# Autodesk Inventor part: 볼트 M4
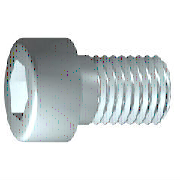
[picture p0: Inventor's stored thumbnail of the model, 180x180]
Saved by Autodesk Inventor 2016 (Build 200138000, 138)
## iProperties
IsCustomPart: 1
Created: 2012-02
Part Number: 볼트 M4
Material: 강철, 연강
Description: 6각머리 태핑 나사
Document SubType Name: Modeling
Standard: KS B 1003
Designer: mduedu
Standards Organization: KS
Language: ko-KR
Size Designation: M 4 x 12
Categories: <MemberInstance><Categories><Category DisplayName="조임쇠" InternalName="e4da775c-781d-43d5-af7c-5136215cf5a6" Mnemonic="FSTN"><Category DisplayName="볼트" InternalN
Density: 1 g/cm^3
Appearance: 강철
Author: mduedu
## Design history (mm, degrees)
sketch "스케치1"
  geometry: L1 (-1, 0)-(12, 0); L2 (12, 0)-(12, 2); L3 (12, 2)-(1.75, 2); L4 (1.75, 2)-(1.32, 2); L5 (1.32, 2)-(0, 2); L6 (0, 2)-(0, 3.5); L7 (0, 3.5)-(-4, 3.5); L8 (-4, 3.5)-(-4, 1.732); L9 (-4, 1.732)-(-2, 1.732); L10 (-2, 1.732)-(-1, 0); L11 (-7.2, 0)-(15.2, 0) reference; L12 (0, -0.7)-(0, 4.2) reference; L13 (1.75, 2)-(0, 2)
  constraints: 22 end point, 6 parallel, 2 collinear, 2 perpendicular, 1 horizontal, 1 point on line
  dimensions: "d1" = 10.25 distance from line of L3.end L2 (= GEL); "d2" = 0.42952 distance of L4.end L3.end (computed from GAL); "d3" = 4 distance between parallel lines of L8 L6 (= KOH); "d4" = 2 distance of L8.end L9.end (= INTI); "d5" = 60 deg angle of L10 L1; "d6" = 4 diameter of L3 L1 (= GD); "d7" = 4 diameter of L5 L1 (= BDM); "d8" = 3.4641 diameter of L9 L1 (= 1.1547 x SW); "d9" = 7 diameter of L7 L1 (= KOD); "d26" = 12 distance between parallel lines of L12 L2 (= NLG)
revolve "본체" sketch "스케치1" stored, may be unused: angle "d10" = 90 deg
sketch "스케치2"
  geometry: L1 (0, -4.9)-(0, 4.9) reference; L2 (-4.9, 0)-(4.9, 0) reference; L3 (1.732, 0)-(0.866, -1.5); L4 (0.866, -1.5)-(-0.866, -1.5); L5 (-0.866, -1.5)-(-1.732, 0); L6 (-1.732, 0)-(-0.866, 1.5); L7 (-0.866, 1.5)-(0.866, 1.5); L8 (0.866, 1.5)-(1.732, 0); 2 further points
  constraints: 12 end point, 1 coincident, 1 horizontal alignment, 1 point on line, 12 other
extrude "슬롯" join sketch "스케치2" stored distance "d11" = 10; taper "d12" = 0 deg
workplane "Work Plane1"
fillet "Fillet2" dims "d30" = 0.1 (= R)
body "Solid1"
fillet "모깎기1" dims "d17" = 0.4 (= RR)
feature "스레드" dims "d13" = 10.25 (= GEL), "d14" = 0
chamfer "모따기1" distance "d15" = 0.42941 (= -0.5 x SPD + 0.5 x GD); stored, may be unused: second distance "d16" = 0.42941 (= GUL), angle "d27" = 45 deg
other parameters: "GD" = 4 (= NND) [user parameter; used in 2 equation terms], "NLG" = 12 [user parameter; used in 1 equation term], "GEL" = 10.25 [user parameter; used in 2 equation terms], "KOD" = 7 [user parameter; used in 1 equation term], "KOH" = 4 [user parameter; used in 1 equation term], "INTI" = 2 [user parameter; used in 1 equation term], "GAL" = 0.42941 (= 0.61345 x PTC) [user parameter; used in 1 equation term], "GUL" = 0.42941 (= 0.61345 x PTC) [user parameter; used in 1 equation term], "BDM" = 4 (= NND) [user parameter; used in 1 equation term], "SW" = 3 [user parameter; used in 2 equation terms], "RR" = 0.4 [user parameter; used in 1 equation term], "SPD" = 3.14117 (= NND - 1.2269 x PTC) [user parameter; used in 1 equation term], "d19" = 0, "d28" = 0, "d29" = 0, "R" = 0.1 [user parameter; used in 1 equation term], "PHH" = 0.2 [user parameter], "GD1" = 3.14117 (= THREADDIA - 1.2269 x PTC) [user parameter], "THREADDIA" = 4 [user parameter; used in 1 equation term], "FAWI" = 45 deg [user parameter], "TPU" = 14.28571 (computed from PTC) [user parameter], "PTC" = 0.7 [user parameter; used in 5 equation terms], "NND" = 4 [user parameter; used in 3 equation terms], "TOA" = 30 deg [user parameter], "E0" = 3.465 (= 1.155 x SW) [user parameter]
